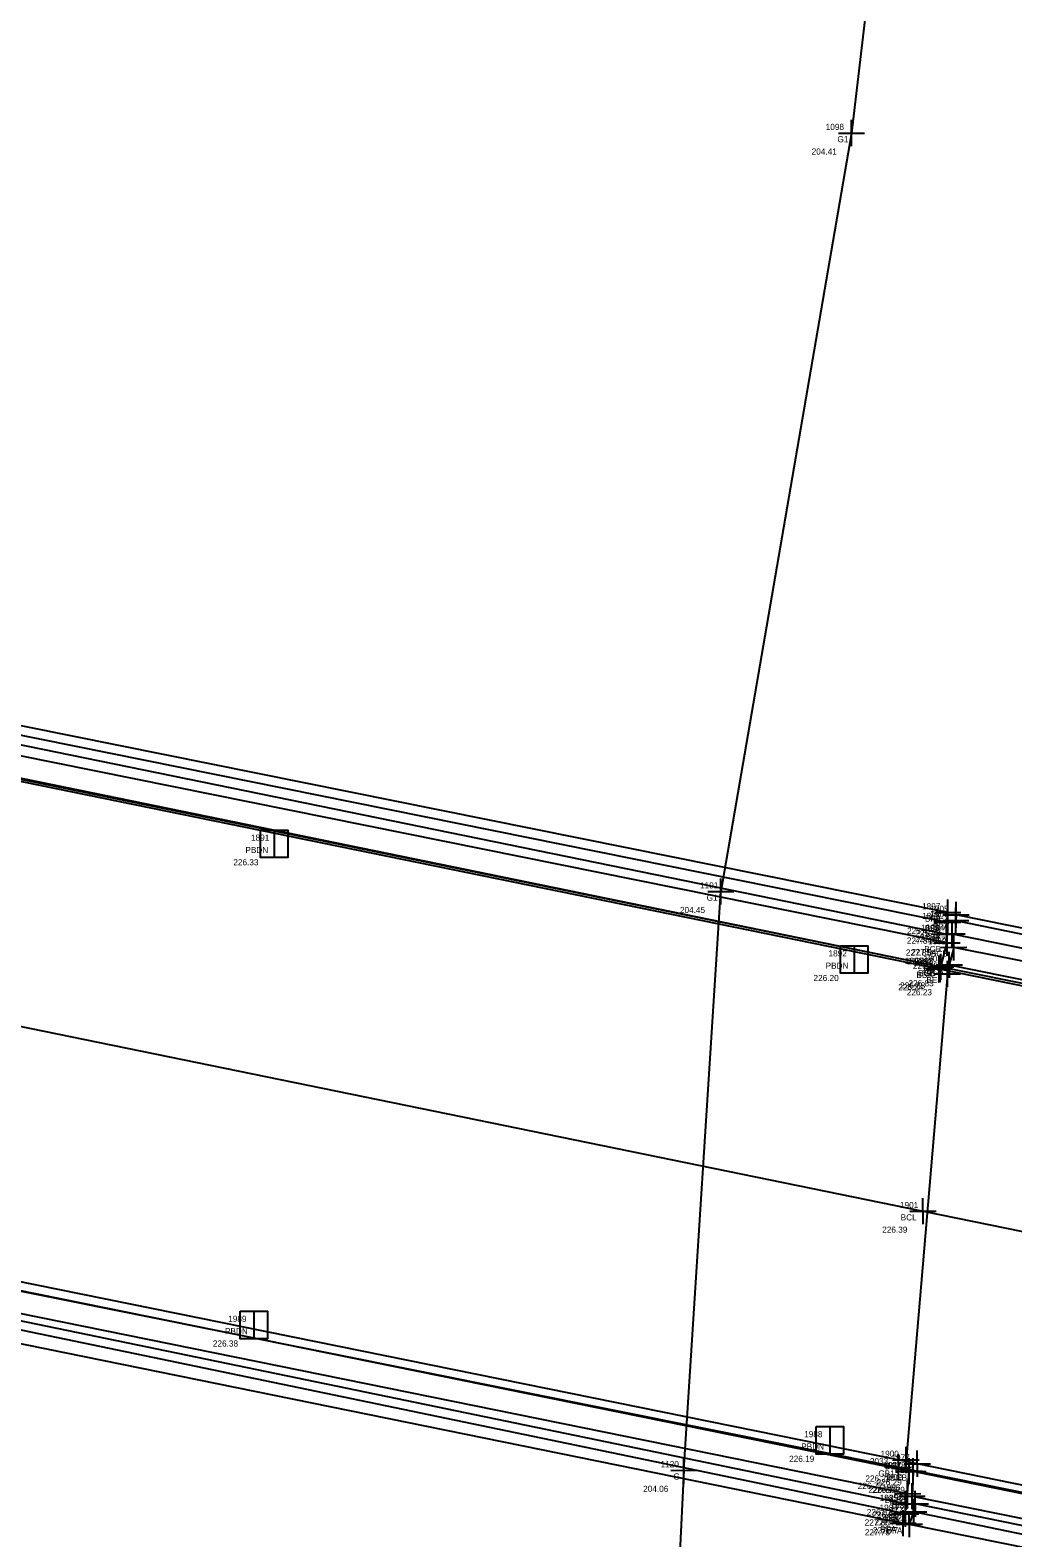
# Model space of a CAD drawing. Extents: x 1158983 to 1160032, y 610902 to 611573.
# Drawn here: x 1159459.3 to 1159507.1, y 611227.2 to 611300.7 of the extents above; entities that cross this region are included whole.
import ezdxf

# ---------------------------------------------------------------- set-up
doc = ezdxf.new("R2010")
doc.units = 0
for name, color, linetype in [('Default', 7, 'Continuous'), ('S_Bridge_Centerline', 7, 'Continuous'), ('S_Bridge_Curb', 7, 'Continuous'), ('S_Bridge_Deck', 7, 'Continuous'), ('S_Bridge_Downspout', 7, 'Continuous'), ('S_Bridge_ExpansionJoint', 7, 'Continuous'), ('S_Bridge_Fascia', 7, 'Continuous'), ('S_Field_Code', 7, 'Continuous'), ('S_Ground_Elevation', 7, 'Continuous'), ('S_Guardrail_Beam', 7, 'Continuous'), ('S_Misc_MiscFeature', 7, 'Continuous'), ('S_Point_Elevation', 7, 'Continuous'), ('S_Point_Name', 7, 'Continuous'), ('S_Survey_Shot', 7, 'Continuous')]:
    doc.layers.add(name, color=color, linetype=linetype)

msp = doc.modelspace()

# ---------------------------------------------------------------- linework, layer by layer
at = {"layer": 'Default'}
for p, q in [((1159471.152, 611261.057), (1159471.152, 611261.057)), ((1159499.422, 611255.42), (1159499.422, 611255.42)), ((1159470.156, 611237.615), (1159470.156, 611237.615)), ((1159498.234, 611231.998), (1159498.234, 611231.998))]:
    msp.add_line(p, q, dxfattribs=at)
at = {"layer": 'S_Bridge_Centerline'}
msp.add_lwpolyline([(1159333.27, 611277.49), (1159375.085, 611269.079), (1159432.648, 611257.515), (1159502.769, 611243.159), (1159572.889, 611228.86), (1159630.259, 611216.999), (1159672.294, 611208.379)], dxfattribs=at)
at = {"layer": 'S_Bridge_Curb'}
for points in [[(1159434.12, 611270.309), (1159434.043, 611269.342), (1159503.64, 611255.058), (1159503.943, 611256.229)], [(1159504.266, 611256.012), (1159504.05, 611255.165), (1159573.73, 611241.065), (1159574.056, 611242.141)], [(1159502.019, 611229.4), (1159502.097, 611230.494), (1159432.384, 611244.643), (1159432.259, 611243.563)], [(1159572.151, 611215.139), (1159572.142, 611216.217), (1159502.289, 611230.486), (1159502.237, 611229.282)]]:
    msp.add_lwpolyline(points, close=True, dxfattribs=at)
at = {"layer": 'S_Bridge_Deck'}
msp.add_lwpolyline([(1159333.801, 611289.348), (1159375.965, 611280.699), (1159433.546, 611269.247), (1159503.551, 611254.972), (1159573.652, 611240.691), (1159630.945, 611229.008), (1159674.004, 611220.503), (1159672.341, 611196.28), (1159630.068, 611204.797), (1159572.75, 611216.514), (1159502.493, 611230.859), (1159432.439, 611245.062), (1159375.072, 611256.503), (1159331.888, 611265.329)], close=True, dxfattribs=at)
at = {"layer": 'S_Bridge_Downspout'}
for p, q in [((1159471.152, 611261.723), (1159471.152, 611260.39)), ((1159499.422, 611256.086), (1159499.422, 611254.753)), ((1159470.156, 611238.282), (1159470.156, 611236.949)), ((1159498.234, 611232.665), (1159498.234, 611231.331))]:
    msp.add_line(p, q, dxfattribs=at)
for points in [[(1159470.485, 611261.723), (1159471.818, 611261.723), (1159471.818, 611260.39), (1159470.485, 611260.39)], [(1159498.755, 611256.086), (1159500.088, 611256.086), (1159500.088, 611254.753), (1159498.755, 611254.753)], [(1159469.489, 611238.282), (1159470.822, 611238.282), (1159470.822, 611236.949), (1159469.489, 611236.949)], [(1159497.568, 611232.665), (1159498.901, 611232.665), (1159498.901, 611231.331), (1159497.568, 611231.331)]]:
    msp.add_lwpolyline(points, close=True, dxfattribs=at)
at = {"layer": 'S_Bridge_ExpansionJoint'}
msp.add_lwpolyline([(1159503.966, 611254.725), (1159501.951, 611231.042)], dxfattribs=at)
at = {"layer": 'S_Bridge_Fascia'}
for points in [[(1159434.373, 611271.73), (1159434.201, 611271.323), (1159503.969, 611257.243), (1159503.98, 611257.715)], [(1159504.379, 611257.596), (1159504.366, 611257.322), (1159574.084, 611243.016), (1159574.172, 611243.474)], [(1159501.804, 611227.968), (1159501.921, 611228.418), (1159432.308, 611242.862), (1159432.108, 611242.134)], [(1159571.895, 611213.806), (1159571.966, 611214.099), (1159502.313, 611228.52), (1159502.102, 611227.909)]]:
    msp.add_lwpolyline(points, close=True, dxfattribs=at)
at = {"layer": 'S_Ground_Elevation'}
for points in [[(1159523.114, 611561.49), (1159514.061, 611512.032), (1159515.186, 611443.046), (1159505.796, 611390.806), (1159504.303, 611338.307), (1159499.282, 611295.679), (1159492.913, 611258.733)], [(1159491.121, 611230.537), (1159492.913, 611258.733)], [(1159491.121, 611230.537), (1159488.281, 611172.56), (1159478.267, 611121.39), (1159473.558, 611065.631), (1159466.706, 611020.412)]]:
    msp.add_lwpolyline(points, dxfattribs=at)
at = {"layer": 'S_Guardrail_Beam'}
for p, q in [((1159433.724, 611269.316), (1159503.64, 611255.058)), ((1159503.64, 611255.058), (1159573.73, 611241.065))]:
    msp.add_line(p, q, dxfattribs=at)
msp.add_lwpolyline([(1159962.355, 611128.723), (1159954.927, 611131.331), (1159940.804, 611136.335), (1159922.846, 611140.981), (1159878.137, 611150.269), (1159824.181, 611161.329), (1159771.192, 611171.967), (1159724.558, 611182.82), (1159696.585, 611190.71), (1159683.564, 611193.82), (1159671.877, 611196.264), (1159629.625, 611204.61), (1159571.633, 611216.492), (1159501.577, 611230.682), (1159431.638, 611244.705), (1159374.182, 611256.374), (1159332.105, 611265.121)], dxfattribs=at)
at = {"layer": 'S_Misc_MiscFeature'}
for points in [[(1159434.199, 611270.905), (1159503.923, 611256.66)], [(1159504.184, 611256.678), (1159574.001, 611242.501)], [(1159501.916, 611228.898), (1159432.353, 611243.274)], [(1159572.107, 611214.695), (1159502.394, 611228.905)]]:
    msp.add_lwpolyline(points, dxfattribs=at)
at = {"layer": 'S_Survey_Shot'}
for p, q in [((1159499.283, 611295.043), (1159499.28, 611296.316)), ((1159498.645, 611295.678), (1159499.918, 611295.681)), ((1159499.282, 611295.679), (1159499.282, 611295.679)), ((1159492.277, 611258.731), (1159493.549, 611258.734)), ((1159492.914, 611258.097), (1159492.912, 611259.369)), ((1159492.913, 611258.733), (1159492.913, 611258.733)), ((1159503.982, 611257.079), (1159503.979, 611258.351)), ((1159504.367, 611256.686), (1159504.365, 611257.958)), ((1159504.38, 611256.96), (1159504.377, 611258.232)), ((1159503.333, 611257.242), (1159504.606, 611257.245)), ((1159503.344, 611257.714), (1159504.617, 611257.716)), ((1159503.73, 611257.32), (1159505.002, 611257.323)), ((1159503.742, 611257.595), (1159505.015, 611257.597)), ((1159503.924, 611256.024), (1159503.921, 611257.297)), ((1159503.971, 611256.607), (1159503.968, 611257.88)), ((1159503.969, 611257.243), (1159503.969, 611257.243)), ((1159503.98, 611257.715), (1159503.98, 611257.715)), ((1159504.185, 611256.042), (1159504.183, 611257.314)), ((1159504.366, 611257.322), (1159504.366, 611257.322)), ((1159504.379, 611257.596), (1159504.379, 611257.596)), ((1159503.286, 611256.659), (1159504.559, 611256.662)), ((1159503.548, 611256.677), (1159504.82, 611256.679)), ((1159503.923, 611256.66), (1159503.923, 611256.66)), ((1159503.944, 611255.593), (1159503.942, 611256.865)), ((1159504.184, 611256.678), (1159504.184, 611256.678)), ((1159504.267, 611255.376), (1159504.264, 611256.649)), ((1159503.307, 611256.228), (1159504.579, 611256.23)), ((1159503.629, 611256.011), (1159504.902, 611256.014)), ((1159503.943, 611256.229), (1159503.943, 611256.229)), ((1159504.052, 611254.529), (1159504.049, 611255.801)), ((1159504.266, 611256.012), (1159504.266, 611256.012)), ((1159503.004, 611255.057), (1159504.277, 611255.059)), ((1159503.004, 611255.057), (1159504.277, 611255.059)), ((1159503.414, 611255.164), (1159504.687, 611255.166)), ((1159503.552, 611254.335), (1159503.549, 611255.608)), ((1159503.642, 611254.422), (1159503.639, 611255.694)), ((1159503.642, 611254.422), (1159503.639, 611255.694)), ((1159503.64, 611255.058), (1159503.64, 611255.058)), ((1159503.64, 611255.058), (1159503.64, 611255.058)), ((1159503.967, 611254.089), (1159503.965, 611255.362)), ((1159504.05, 611255.165), (1159504.05, 611255.165)), ((1159502.914, 611254.97), (1159504.187, 611254.973)), ((1159503.33, 611254.724), (1159504.602, 611254.727)), ((1159503.551, 611254.972), (1159503.551, 611254.972)), ((1159503.966, 611254.725), (1159503.966, 611254.725)), ((1159502.77, 611242.522), (1159502.768, 611243.795)), ((1159502.133, 611243.157), (1159503.405, 611243.16)), ((1159502.769, 611243.159), (1159502.769, 611243.159)), ((1159501.953, 611230.405), (1159501.95, 611231.678)), ((1159491.122, 611229.9), (1159491.119, 611231.173)), ((1159501.315, 611231.04), (1159502.588, 611231.043)), ((1159501.579, 611230.046), (1159501.576, 611231.318)), ((1159501.857, 611230.857), (1159503.129, 611230.86)), ((1159501.951, 611231.042), (1159501.951, 611231.042)), ((1159502.099, 611229.858), (1159502.096, 611231.131)), ((1159502.291, 611229.849), (1159502.288, 611231.122)), ((1159502.495, 611230.223), (1159502.492, 611231.495)), ((1159502.493, 611230.859), (1159502.493, 611230.859)), ((1159490.484, 611230.535), (1159491.757, 611230.538)), ((1159491.121, 611230.537), (1159491.121, 611230.537)), ((1159500.941, 611230.68), (1159502.214, 611230.683)), ((1159501.461, 611230.493), (1159502.733, 611230.496)), ((1159501.577, 611230.682), (1159501.577, 611230.682)), ((1159501.653, 611230.484), (1159502.926, 611230.487)), ((1159502.02, 611228.764), (1159502.017, 611230.036)), ((1159502.097, 611230.494), (1159502.097, 611230.494)), ((1159502.289, 611230.486), (1159502.289, 611230.486)), ((1159501.382, 611229.399), (1159502.655, 611229.401)), ((1159501.918, 611228.262), (1159501.915, 611229.534)), ((1159502.019, 611229.4), (1159502.019, 611229.4)), ((1159502.238, 611228.646), (1159502.235, 611229.918)), ((1159502.396, 611228.269), (1159502.393, 611229.541)), ((1159501.28, 611228.896), (1159502.552, 611228.899)), ((1159501.601, 611229.281), (1159502.873, 611229.284)), ((1159501.758, 611228.904), (1159503.031, 611228.906)), ((1159501.806, 611227.331), (1159501.803, 611228.604)), ((1159501.916, 611228.898), (1159501.916, 611228.898)), ((1159501.923, 611227.782), (1159501.92, 611229.054)), ((1159502.237, 611229.282), (1159502.237, 611229.282)), ((1159502.314, 611227.883), (1159502.312, 611229.156)), ((1159502.394, 611228.905), (1159502.394, 611228.905)), ((1159501.168, 611227.966), (1159502.441, 611227.969)), ((1159501.285, 611228.416), (1159502.558, 611228.419)), ((1159501.466, 611227.908), (1159502.739, 611227.911)), ((1159501.677, 611228.518), (1159502.949, 611228.521)), ((1159501.804, 611227.968), (1159501.804, 611227.968)), ((1159501.921, 611228.418), (1159501.921, 611228.418)), ((1159502.104, 611227.273), (1159502.101, 611228.546)), ((1159502.102, 611227.909), (1159502.102, 611227.909)), ((1159502.313, 611228.52), (1159502.313, 611228.52))]:
    msp.add_line(p, q, dxfattribs=at)

# ---------------------------------------------------------------- texts
at = {"layer": 'S_Field_Code'}
for s, p in [('G1', (1159498.597, 611295.229)), ('PBDN', (1159469.751, 611260.607)), ('G1', (1159492.228, 611258.283)), ('BFA', (1159502.863, 611257.265)), ('BFA', (1159503.261, 611257.146)), ('BFA', (1159502.852, 611256.793)), ('ZZ', (1159503.122, 611256.21)), ('BFA', (1159503.249, 611256.872)), ('ZZ', (1159503.383, 611256.228)), ('BCB', (1159502.828, 611255.779)), ('BCB', (1159503.151, 611255.562)), ('PBDN', (1159498.021, 611254.97)), ('BCB', (1159502.935, 611254.715)), ('BDK', (1159502.45, 611254.522)), ('BCB', (1159502.525, 611254.608)), ('GB', (1159502.825, 611254.608)), ('BEJ', (1159502.936, 611254.275)), ('BCL', (1159501.682, 611242.709)), ('PBDN', (1159468.755, 611237.165)), ('PBDN', (1159496.833, 611231.548)), ('BEJ', (1159500.922, 611230.592)), ('G', (1159490.606, 611230.087)), ('GB1', (1159500.592, 611230.232)), ('BCB', (1159500.982, 611230.044)), ('BCB', (1159501.174, 611230.036)), ('BDK', (1159501.392, 611230.409)), ('BCB', (1159500.904, 611228.95)), ('ZZ', (1159501.115, 611228.448)), ('BCB', (1159501.122, 611228.832)), ('ZZ', (1159501.594, 611228.455)), ('BFA', (1159500.804, 611227.968)), ('BFA', (1159501.196, 611228.07)), ('BFA', (1159500.687, 611227.518)), ('BFA', (1159500.985, 611227.459))]:
    msp.add_text(s, height=0.3, dxfattribs=at).set_placement(p)
at = {"layer": 'S_Point_Elevation'}
for s, p in [('204.41', (1159497.342, 611294.629)), ('226.33', (1159469.163, 611260.007)), ('204.45', (1159490.924, 611257.683)), ('227.84', (1159501.981, 611256.193)), ('225.42', (1159501.992, 611256.665)), ('227.84', (1159502.377, 611256.272)), ('225.43', (1159502.39, 611256.546)), ('227.85', (1159501.934, 611255.61)), ('227.84', (1159502.195, 611255.628)), ('226.91', (1159502.004, 611255.179)), ('226.85', (1159502.277, 611254.962)), ('226.20', (1159497.433, 611254.37)), ('226.83', (1159501.651, 611254.008)), ('226.83', (1159501.651, 611254.008)), ('226.83', (1159502.061, 611254.115)), ('226.24', (1159501.562, 611253.922)), ('226.23', (1159501.977, 611253.675)), ('226.39', (1159500.78, 611242.109)), ('226.38', (1159468.167, 611236.565)), ('226.19', (1159496.245, 611230.948)), ('226.28', (1159499.963, 611229.992)), ('226.29', (1159500.504, 611229.809)), ('204.06', (1159489.132, 611229.487)), ('226.77', (1159499.588, 611229.632)), ('226.77', (1159500.108, 611229.444)), ('226.76', (1159500.3, 611229.436)), ('226.82', (1159500.03, 611228.35)), ('227.80', (1159499.927, 611227.848)), ('226.81', (1159500.297, 611228.232)), ('227.78', (1159500.405, 611227.855)), ('227.78', (1159499.932, 611227.368)), ('227.77', (1159500.324, 611227.47))]:
    msp.add_text(s, height=0.3, dxfattribs=at).set_placement(p)
at = {"layer": 'S_Point_Name'}
for s, p in [('1098', (1159498.027, 611295.829)), ('1891', (1159470.025, 611261.207)), ('1101', (1159491.904, 611258.883)), ('1897', (1159502.722, 611257.865)), ('1905', (1159503.124, 611257.746)), ('1896', (1159502.727, 611257.393)), ('1906', (1159503.126, 611257.472)), ('1895', (1159502.666, 611256.81)), ('1894', (1159502.672, 611256.379)), ('1904', (1159502.916, 611256.828)), ('1892', (1159498.165, 611255.57)), ('1902', (1159503.011, 611256.162)), ('1893_1', (1159501.885, 611255.208)), ('1898', (1159502.294, 611255.122)), ('1893', (1159502.384, 611255.208)), ('1899', (1159502.724, 611254.875)), ('1903', (1159502.796, 611255.315)), ('1901', (1159501.645, 611243.309)), ('1989', (1159468.913, 611237.765)), ('1988', (1159496.978, 611232.148)), ('1120', (1159489.982, 611230.687)), ('2033', (1159500.179, 611230.832)), ('1900', (1159500.7, 611231.192)), ('1987', (1159500.838, 611230.644)), ('1978', (1159501.03, 611230.636)), ('1977', (1159501.232, 611231.009)), ('1985', (1159500.66, 611229.048)), ('1986', (1159500.776, 611229.55)), ('1979', (1159500.992, 611229.432)), ('1980', (1159501.14, 611229.055)), ('1984', (1159500.651, 611228.568)), ('1981', (1159501.186, 611228.67)), ('1983', (1159500.548, 611228.118)), ('1982', (1159500.846, 611228.059))]:
    msp.add_text(s, height=0.3, dxfattribs=at).set_placement(p)

doc.saveas('drawing.dxf')
